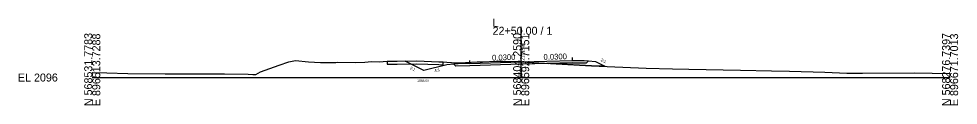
# Model space of a CAD drawing. Extents: x -26 to 1603, y -10 to 13527.
# Drawn here: x -25.7 to 302.8, y 9990.3 to 10020.6 of the extents above; entities that cross this region are included whole.
import ezdxf

# ---------------------------------------------------------------- set-up
doc = ezdxf.new("R2010")
doc.units = 0
for name, color, linetype in [('Default', 7, 'Continuous'), ('Exist XS Center Line Elevation Label', 7, 'Continuous'), ('Exist XS Ground Line', 7, 'Continuous'), ('Old_Level_61', 7, 'Continuous'), ('Old_Level_63', 7, 'Continuous'), ('Prop XS Ditch Slope Text', 7, 'Continuous'), ('Prop XS Ditch Standard Text', 7, 'Continuous'), ('Prop XS Earthwork Shape', 7, 'Continuous'), ('Prop XS EOT Tick Mark', 7, 'Continuous'), ('Prop XS Finish Grade', 7, 'Continuous'), ('Prop XS Finish Grade Earthwork', 7, 'Continuous'), ('Prop XS Finish Grade Paved Shoulder', 7, 'Continuous'), ('Prop XS Finish Grade Pavement', 7, 'Continuous'), ('Prop XS Side Slope Text', 7, 'Continuous'), ('Prop XS Subgrade Earthwork', 7, 'Continuous'), ('Prop XSC Text', 7, 'Continuous')]:
    doc.layers.add(name, color=color, linetype=linetype)

msp = doc.modelspace()

# ---------------------------------------------------------------- linework, layer by layer
at = {"layer": 'Exist XS Ground Line'}
for p, q in [((58.87, 10002.02), (65.38, 10004.38)), ((65.38, 10004.38), (68.78, 10005.49)), ((68.78, 10005.49), (71.08, 10005.93)), ((71.08, 10005.93), (75.59, 10005.56)), ((75.59, 10005.56), (79.87, 10005.25)), ((79.87, 10005.25), (85.19, 10005.32)), ((85.19, 10005.32), (85.86, 10005.35)), ((85.86, 10005.35), (92.02, 10005.28)), ((92.02, 10005.28), (95.33, 10005.44)), ((95.33, 10005.44), (97.62, 10005.58)), ((97.62, 10005.58), (100.57, 10005.54)), ((100.57, 10005.54), (101.72, 10005.58)), ((101.72, 10005.58), (103.18, 10005.68)), ((103.18, 10005.68), (106.61, 10005.72)), ((106.61, 10005.72), (113.51, 10005.83)), ((113.51, 10005.83), (121.18, 10005.56)), ((121.18, 10005.56), (122.75, 10005.51)), ((122.75, 10005.51), (123.99, 10005.4)), ((123.99, 10005.4), (127.22, 10005.13)), ((127.22, 10005.13), (128.15, 10005.18)), ((128.15, 10005.18), (130.54, 10005.27)), ((130.54, 10005.27), (134.57, 10005.46)), ((134.57, 10005.46), (136.01, 10005.51)), ((136.01, 10005.51), (136.43, 10005.5)), ((136.43, 10005.5), (141.26, 10005.71)), ((141.26, 10005.71), (143.71, 10005.7)), ((143.71, 10005.7), (147.77, 10005.59)), ((147.77, 10005.59), (150, 10005.48)), ((150, 10005.48), (172.55, 10004.27)), ((172.55, 10004.27), (174.62, 10004.16)), ((174.62, 10004.16), (193.75, 10003.32)), ((0, 10001.81), (0.08, 10001.81)), ((0.08, 10001.81), (5.12, 10001.66)), ((5.12, 10001.66), (12.43, 10001.4)), ((12.43, 10001.4), (25.53, 10001.29)), ((25.53, 10001.29), (32.42, 10001.31)), ((32.42, 10001.31), (34.98, 10001.31)), ((34.98, 10001.31), (40.23, 10001.29)), ((40.23, 10001.29), (42.29, 10001.29)), ((42.29, 10001.29), (46.24, 10001.31)), ((46.24, 10001.31), (54.51, 10001.15)), ((54.51, 10001.15), (56.2, 10001.09)), ((56.2, 10001.09), (57.19, 10001.05)), ((57.19, 10001.05), (58.87, 10002.02)), ((193.75, 10003.32), (202.92, 10003.05)), ((202.92, 10003.05), (208.68, 10002.98)), ((208.68, 10002.98), (226.73, 10002.53)), ((226.73, 10002.53), (237.58, 10002.34)), ((237.58, 10002.34), (243.82, 10002.18)), ((243.82, 10002.18), (256.23, 10001.83)), ((256.23, 10001.83), (263.84, 10001.59)), ((263.84, 10001.59), (269.35, 10001.51)), ((269.35, 10001.51), (287.46, 10001.64)), ((287.46, 10001.64), (300, 10001.37))]:
    msp.add_line(p, q, dxfattribs=at)
at = {"layer": 'Old_Level_61'}
for p, q in [((103.18, 10005.68), (103.18, 10004.68)), ((103.18, 10004.68), (104.19, 10004.69)), ((104.19, 10004.69), (106.61, 10004.72)), ((106.61, 10004.72), (113.51, 10004.83)), ((113.51, 10004.83), (121.18, 10004.56)), ((121.18, 10004.56), (122.75, 10004.51)), ((122.75, 10004.51), (122.77, 10004.51)), ((122.77, 10004.51), (122.77, 10005.51))]:
    msp.add_line(p, q, dxfattribs=at)
at = {"layer": 'Old_Level_63'}
for p, q in [((150, 10000), (150, 10017.78)), ((0, 10000), (150, 10000)), ((150, 10000), (300, 10000))]:
    msp.add_line(p, q, dxfattribs=at)
at = {"layer": 'Prop XS Earthwork Shape'}
for points in [[(116, 10002.52), (109.42, 10005.76), (113.51, 10005.83), (121.18, 10005.56), (122.75, 10005.51), (123.99, 10005.4), (127.22, 10005.13), (128.15, 10005.18), (130.54, 10005.27), (134.57, 10005.46), (136.01, 10005.51), (136.43, 10005.5), (141.26, 10005.71), (143.71, 10005.7), (147.77, 10005.59), (150, 10005.48), (159.69, 10004.96), (150, 10004.67), (132, 10004.13), (127.12, 10003.98), (126.41, 10004.68), (124, 10004.49)], [(168, 10005.21), (172.81, 10005.11), (173.5, 10005.8), (176, 10005.6), (179.29, 10003.95), (174.62, 10004.16), (172.55, 10004.27), (159.69, 10004.96)]]:
    msp.add_lwpolyline(points, close=True, dxfattribs=at)
at = {"layer": 'Prop XS EOT Tick Mark'}
for p, q in [((132, 10004.92), (132, 10005.92)), ((168, 10006), (168, 10007))]:
    msp.add_line(p, q, dxfattribs=at)
at = {"layer": 'Prop XS Finish Grade'}
for p, q in [((127.94, 10004.8), (126.41, 10004.68)), ((172, 10005.92), (173.5, 10005.8))]:
    msp.add_line(p, q, dxfattribs=at)
at = {"layer": 'Prop XS Finish Grade Earthwork'}
for p, q in [((116, 10002.52), (109.42, 10005.76)), ((124, 10004.49), (116, 10002.52)), ((126.41, 10004.68), (124, 10004.49)), ((173.5, 10005.8), (176, 10005.6)), ((176, 10005.6), (179.29, 10003.95))]:
    msp.add_line(p, q, dxfattribs=at)
at = {"layer": 'Prop XS Finish Grade Paved Shoulder'}
for p, q in [((132, 10004.92), (127.94, 10004.8)), ((168, 10006), (172, 10005.92))]:
    msp.add_line(p, q, dxfattribs=at)
at = {"layer": 'Prop XS Finish Grade Pavement'}
for p, q in [((132, 10004.92), (150, 10005.46)), ((150, 10005.46), (168, 10006))]:
    msp.add_line(p, q, dxfattribs=at)
at = {"layer": 'Prop XS Subgrade Earthwork'}
for p, q in [((127.12, 10003.98), (126.41, 10004.68)), ((132, 10004.13), (127.12, 10003.98)), ((150, 10004.67), (132, 10004.13)), ((168, 10005.21), (150, 10004.67)), ((168, 10005.21), (172.81, 10005.11)), ((172.81, 10005.11), (173.5, 10005.8))]:
    msp.add_line(p, q, dxfattribs=at)

# ---------------------------------------------------------------- texts
at = {"layer": 'Default'}
for p in [(139.84, 10005.94), (157.84, 10006.19)]:
    msp.add_text('0.0300', height=2, rotation=1.7184, dxfattribs=at).set_placement(p)
at = {"layer": 'Exist XS Center Line Elevation Label'}
msp.add_text('2101.48', height=1, rotation=90, dxfattribs=at).set_placement((150.5, 9998.23))
at = {"layer": 'Old_Level_63'}
for s, p in [('L', (140, 10017.78)), ('22+50.00 / 1', (140, 10014.98)), ('EL 2096', (-26, 9998.6))]:
    msp.add_text(s, height=2.8, dxfattribs=at).set_placement(p)
for s, p in [('N 568531.7783', (0, 9990)), ('E 896513.7288', (2.8, 9990)), ('N 568404.2590', (150, 9990)), ('E 896592.7151', (152.8, 9990)), ('N 568276.7397', (300, 9990)), ('E 896671.7013', (302.8, 9990))]:
    msp.add_text(s, height=2.8, rotation=90, dxfattribs=at).set_placement(p)
at = {"layer": 'Prop XS Ditch Slope Text'}
msp.add_text('4:1', height=1, rotation=13.8523, dxfattribs=at).set_placement((119.81, 10001.86))
at = {"layer": 'Prop XS Ditch Standard Text'}
msp.add_text('2098.50', height=0.8, dxfattribs=at).set_placement((113.69, 9998.48))
at = {"layer": 'Prop XS Side Slope Text'}
for rotation, p in [(333.4349, (177.72, 10005.86)), (333.7483, (110.97, 10002.99))]:
    msp.add_text('2:1', height=1, rotation=rotation, dxfattribs=at).set_placement(p)
at = {"layer": 'Prop XSC Text'}
msp.add_text(' 2101.46', height=1.2, rotation=90, dxfattribs=at).set_placement((151.2, 10005.46))

doc.saveas('drawing.dxf')
